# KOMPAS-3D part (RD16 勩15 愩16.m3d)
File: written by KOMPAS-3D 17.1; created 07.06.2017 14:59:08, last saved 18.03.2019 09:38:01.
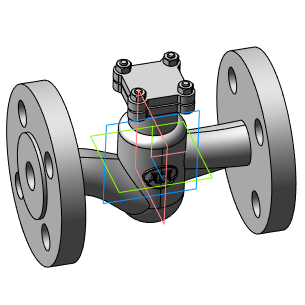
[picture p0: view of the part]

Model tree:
1. Операция без истории:2  (labels: Сталь 20  ГОСТ 1050-88)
